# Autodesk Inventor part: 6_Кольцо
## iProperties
Created: 2009-12
Part Number: 6_Кольцо
Document SubType Name: Modeling
Designer: Jeck
Density: 1 g/cm^3
Mass: 9.92006 g
Surface Area: 47.4102 cm^2
Volume: 9.92006 cm^3
Author: Jeck
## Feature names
1. Выдавливание1 [Extrusion]
2. Отверстие1 [Hole]
